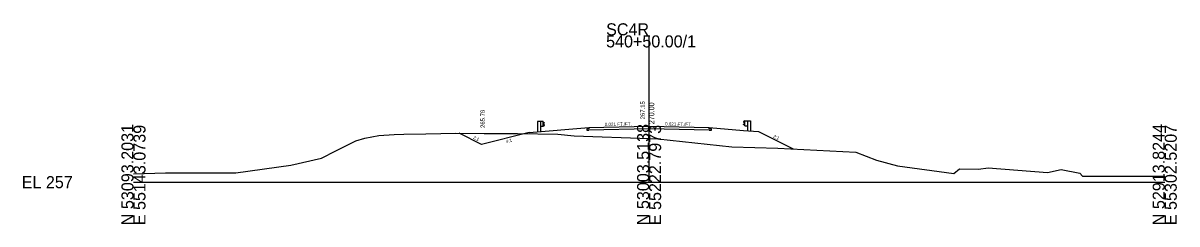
# Model space of a CAD drawing. Extents: x 9740 to 17409, y 8856 to 28416.
# Drawn here: x 11740.2 to 12008.7, y 21361.7 to 21408.3 of the extents above; entities that cross this region are included whole.
import ezdxf

# ---------------------------------------------------------------- set-up
doc = ezdxf.new("R2010")
doc.units = 0
for name, color, linetype in [('Level 10', 7, 'Continuous'), ('Level 11', 7, 'Continuous'), ('Level 12', 7, 'Continuous'), ('Level 24', 7, 'Continuous'), ('Level 32', 7, 'Continuous'), ('Level 33', 7, 'Continuous'), ('Level 59', 7, 'Continuous'), ('Level 6', 7, 'Continuous'), ('Level 60', 7, 'Continuous'), ('Level 63', 7, 'Continuous'), ('Level 7', 7, 'Continuous')]:
    doc.layers.add(name, color=color, linetype=linetype)

msp = doc.modelspace()

# ---------------------------------------------------------------- linework, layer by layer
at = {"layer": 'Level 11'}
for p, q in [((11871.85, 21383.79), (11871.35, 21383.78)), ((11871.35, 21383.78), (11871.35, 21383.44)), ((11871.35, 21383.44), (11871.85, 21383.45)), ((11871.85, 21384.09), (11871.85, 21383.79)), ((11899.85, 21383.79), (11899.85, 21384.09)), ((11900.35, 21383.78), (11899.85, 21383.79)), ((11899.85, 21383.45), (11900.35, 21383.44)), ((11900.35, 21383.44), (11900.35, 21383.78))]:
    msp.add_line(p, q, dxfattribs=at)
at = {"layer": 'Level 12'}
for p, q in [((11885.85, 21383.74), (11871.85, 21383.45)), ((11899.85, 21383.45), (11885.85, 21383.74))]:
    msp.add_line(p, q, dxfattribs=at)
at = {"layer": 'Level 24'}
for p, q in [((11860.54, 21385.47), (11859.87, 21385.47)), ((11859.87, 21385.47), (11859.87, 21383.09)), ((11861.21, 21385.47), (11860.54, 21385.47)), ((11860.54, 21385.47), (11860.54, 21383.15)), ((11861.21, 21384.31), (11860.54, 21384.31)), ((11861.21, 21384.31), (11861.21, 21385.47)), ((11861.21, 21385.4), (11861.48, 21385.2)), ((11861.48, 21385.15), (11861.21, 21384.95)), ((11861.48, 21384.63), (11861.21, 21384.83)), ((11861.21, 21384.38), (11861.48, 21384.58)), ((11861.48, 21385.2), (11861.48, 21385.15)), ((11861.48, 21384.58), (11861.48, 21384.63)), ((11908.12, 21385.6), (11907.85, 21385.4)), ((11907.85, 21385.4), (11907.85, 21385.35)), ((11907.85, 21385.35), (11908.12, 21385.15)), ((11907.85, 21384.83), (11908.12, 21385.03)), ((11907.85, 21384.78), (11907.85, 21384.83)), ((11908.12, 21384.58), (11907.85, 21384.78)), ((11908.12, 21384.51), (11908.12, 21385.67)), ((11908.12, 21385.67), (11908.79, 21385.67)), ((11908.12, 21384.51), (11908.79, 21384.51)), ((11908.79, 21385.67), (11908.79, 21383.34)), ((11908.79, 21385.67), (11909.46, 21385.67)), ((11909.46, 21385.67), (11909.46, 21383.29))]:
    msp.add_line(p, q, dxfattribs=at)
at = {"layer": 'Level 59'}
for p, q in [((11871.85, 21384.09), (11885.85, 21384.38)), ((11885.85, 21384.38), (11899.85, 21384.09))]:
    msp.add_line(p, q, dxfattribs=at)
at = {"layer": 'Level 6'}
for p, q in [((11857.97, 21382.93), (11871.85, 21384.09)), ((11899.85, 21384.09), (11907.85, 21383.42)), ((11907.85, 21383.42), (11911.35, 21383.13))]:
    msp.add_line(p, q, dxfattribs=at)
at = {"layer": 'Level 60'}
for p, q in [((11812.97, 21378.67), (11817.59, 21380.98)), ((11817.59, 21380.98), (11819.71, 21381.6)), ((11819.71, 21381.6), (11822.95, 21382.2)), ((11822.95, 21382.2), (11826.5, 21382.44)), ((11826.5, 21382.44), (11828.78, 21382.52)), ((11828.78, 21382.52), (11833.89, 21382.61)), ((11833.89, 21382.61), (11840.87, 21382.75)), ((11840.87, 21382.75), (11847.48, 21382.72)), ((11847.48, 21382.72), (11852.16, 21382.66)), ((11852.16, 21382.66), (11855.21, 21382.7)), ((11855.21, 21382.7), (11864.62, 21382.52)), ((11864.62, 21382.52), (11868.44, 21382.13)), ((11868.44, 21382.13), (11885.85, 21381.53)), ((11885.85, 21381.53), (11887.88, 21381.46)), ((11887.88, 21381.46), (11905.1, 21379.6)), ((11809.59, 21376.98), (11812.97, 21378.67)), ((11905.1, 21379.6), (11915.83, 21379.28)), ((11915.83, 21379.28), (11933.99, 21378.34)), ((11933.99, 21378.34), (11938.81, 21376.49)), ((11802.46, 21375.3), (11809.59, 21376.98)), ((11938.81, 21376.49), (11943.69, 21375.14)), ((11765.85, 21373.32), (11773.29, 21373.53)), ((11773.29, 21373.53), (11789.66, 21373.57)), ((11789.66, 21373.57), (11802.46, 21375.3)), ((11943.69, 21375.14), (11956.76, 21373.42)), ((11956.76, 21373.42), (11958.08, 21374.48)), ((11958.08, 21374.48), (11962.53, 21374.42)), ((11962.53, 21374.42), (11964.77, 21374.73)), ((11964.77, 21374.73), (11978.6, 21373.63)), ((11978.6, 21373.63), (11981.72, 21374.29)), ((11981.72, 21374.29), (11986.12, 21373.47)), ((11986.12, 21373.47), (11986.68, 21372.81)), ((11986.68, 21372.81), (12001.63, 21372.78)), ((12001.63, 21372.78), (12005.85, 21372.78))]:
    msp.add_line(p, q, dxfattribs=at)
at = {"layer": 'Level 63'}
for p, q in [((11885.85, 21371.38), (11885.85, 21405.5)), ((11765.85, 21371.38), (11885.85, 21371.38)), ((11885.85, 21371.38), (12005.85, 21371.38))]:
    msp.add_line(p, q, dxfattribs=at)
at = {"layer": 'Level 7'}
for p, q in [((11846.86, 21380.16), (11841.67, 21382.75)), ((11857.97, 21382.93), (11846.86, 21380.16)), ((11911.35, 21383.13), (11919.42, 21379.1))]:
    msp.add_line(p, q, dxfattribs=at)

# ---------------------------------------------------------------- texts
at = {"layer": 'Level 10'}
msp.add_text('267.15', height=1, rotation=90, dxfattribs=at).set_placement((11884.85, 21385.97))
at = {"layer": 'Level 32'}
for s, rotation, p in [('0.021 FT./FT.', 1.1916, (11875.56, 21384.42)), ('0.021 FT./FT.', 358.8084, (11889.57, 21384.55)), ('2:1', 333.435, (11844.8, 21381.54)), ('4:1', 14.0362, (11852.63, 21380.45)), ('2:1', 333.435, (11914.64, 21381.79))]:
    msp.add_text(s, height=0.75, rotation=rotation, dxfattribs=at).set_placement(p)
at = {"layer": 'Level 33'}
msp.add_text('265.78', height=1, rotation=90, dxfattribs=at).set_placement((11847.61, 21383.98))
at = {"layer": 'Level 59'}
msp.add_text(' 270.00', height=1.2, rotation=90, dxfattribs=at).set_placement((11887.05, 21384.38))
at = {"layer": 'Level 63'}
for s, p in [('SC4R', (11875.85, 21405.5)), ('540+50.00/1', (11875.85, 21402.7)), ('EL 257', (11739.85, 21369.98))]:
    msp.add_text(s, height=2.8, dxfattribs=at).set_placement(p)
for s, p in [('N 53093.2031', (11765.85, 21361.38)), ('E 55143.0739', (11768.65, 21361.38)), ('N 53003.5138', (11885.85, 21361.38)), ('E 55222.7973', (11888.65, 21361.38)), ('N 52913.8244', (12005.85, 21361.38)), ('E 55302.5207', (12008.65, 21361.38))]:
    msp.add_text(s, height=2.8, rotation=90, dxfattribs=at).set_placement(p)

doc.saveas('drawing.dxf')
